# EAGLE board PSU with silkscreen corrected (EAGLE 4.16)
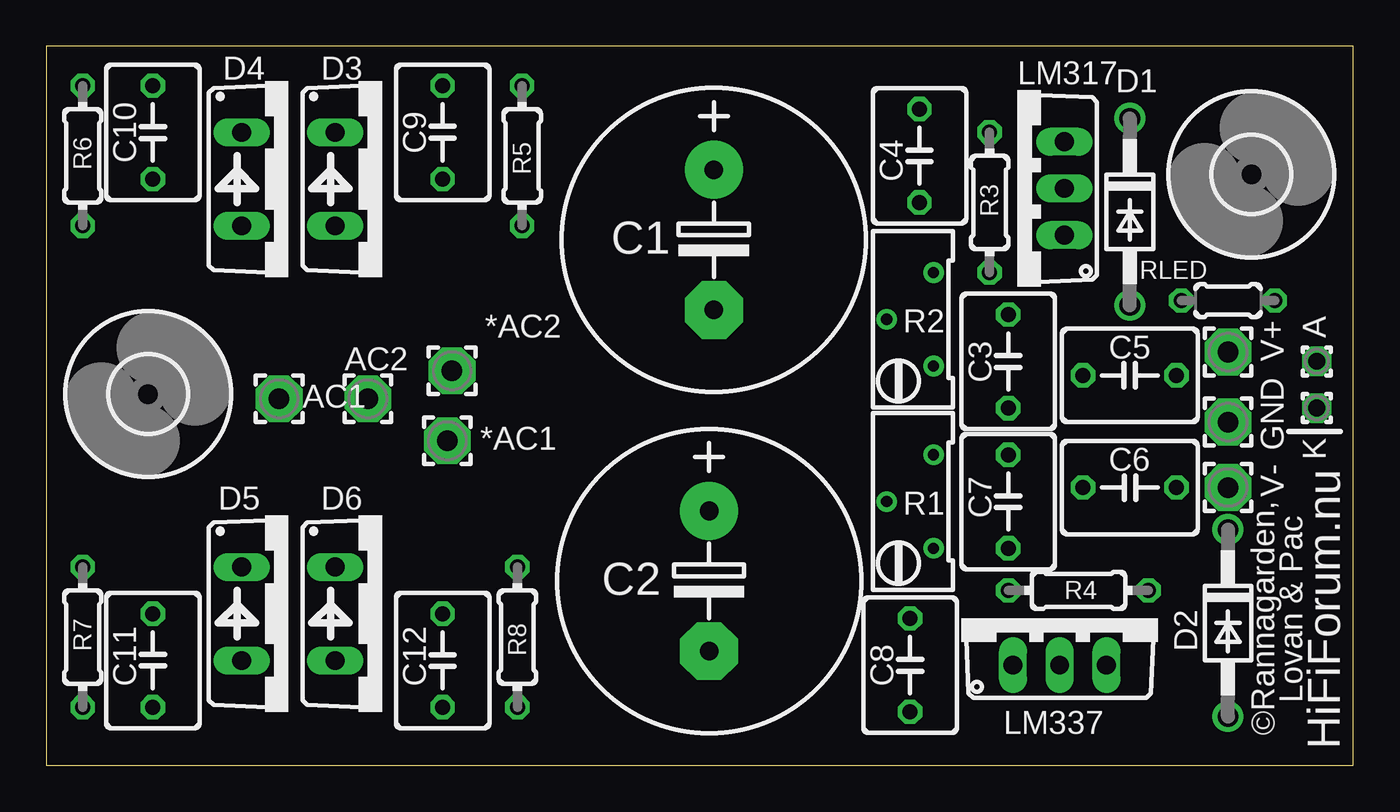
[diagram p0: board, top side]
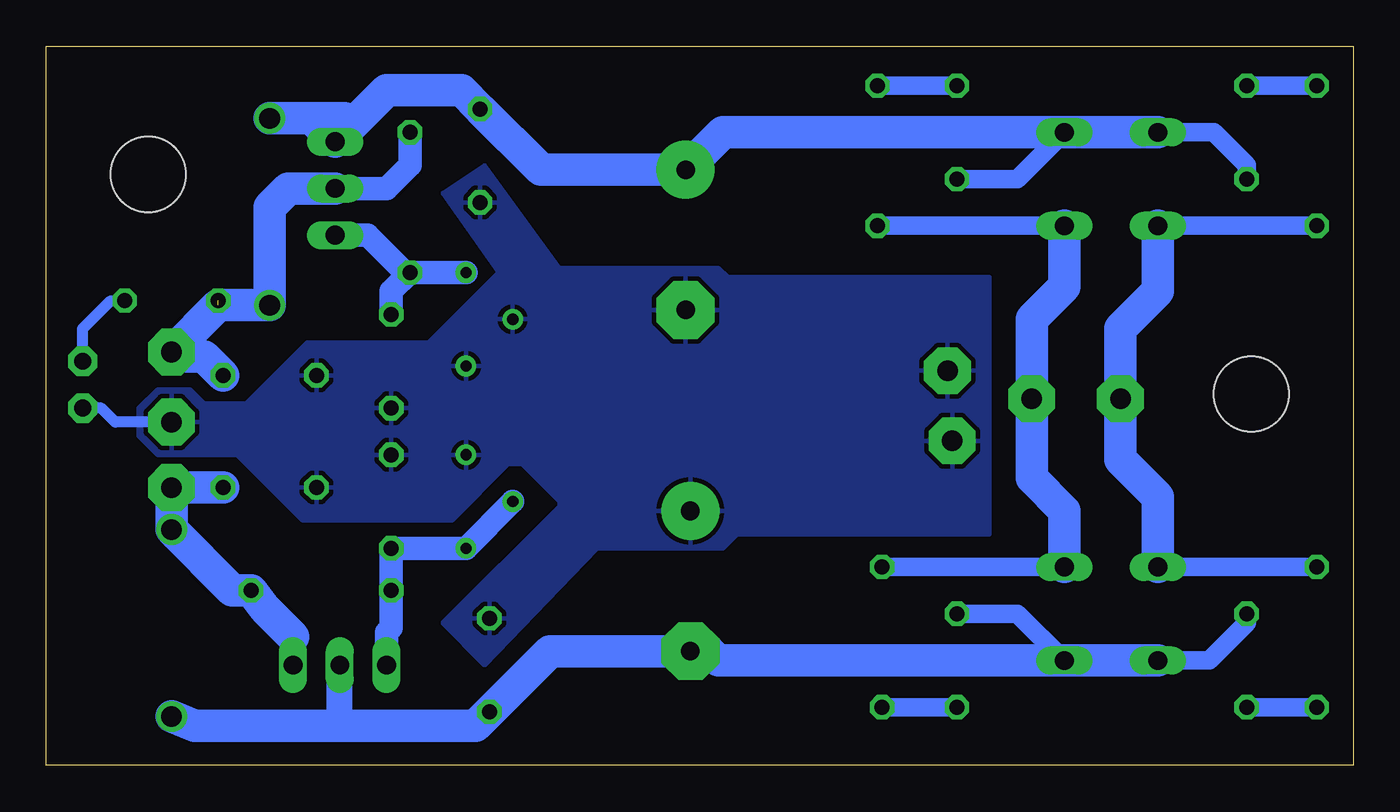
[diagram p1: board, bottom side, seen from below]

Size 71.04 x 39.11 mm. Coordinates in mm from the lower left corner, seen from the top.
Outline: 0,0 71.04,0 71.04,39.11 0,39.11 0,0
Copper layers (1*16): Top 0.035mm / dielectric 1.5mm / Bottom 0.035mm
Design rules "10mils": minimum track width 10mil, minimum drill 24mil, track to track 10mil, track to pad 10mil, pad to pad 10mil, via to via 10mil, smd to smd 10mil, copper to edge 40mil, drill to drill 10mil, minimum pad ring 10mil, minimum via ring 8mil, stop-mask expansion 0mil, vias tented up to drill 0mil, thermal gap 10mil

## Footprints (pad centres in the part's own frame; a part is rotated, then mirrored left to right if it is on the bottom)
2,54/1,1 = drill 1.118 pad 2.54 octagon: 1 0,0
1,6/0,9 = drill 0.914 pad 1.6 octagon: 1 0,0
E7,5-16 = drill 1.016 pad 3.15 round: + -3.81,0 | drill 1.016 pad 3.15 octagon: - 3.81,0
C050-050X075 = drill 0.813 octagon: 1 -2.54,0; 2 2.54,0
DO41-10 = drill 1.118 round: A 5.08,0; C -5.08,0
DO220S = drill 1.016 long: A 2.54,-2.54; C -2.54,-2.54
TO220V = drill 1.016 long: 1 -2.54,-2.54; 2 0,-2.54; 3 2.54,-2.54
RTRIM64Y = drill 0.61 round: 1 0,-2.54; 2 -2.54,0; 3 0,2.54
0204/7 = drill 0.813 octagon: 1 -3.81,0; 2 3.81,0
0204/5 = drill 0.813 octagon: 1 -2.54,0; 2 2.54,0
4,1 = hole 4.1: 0,0

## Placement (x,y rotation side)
*AC1  [2,54/1,1]  21.81,17.65 0 top
*AC2  [2,54/1,1]  22.06,21.46 0 top
A  [1,6/0,9]  69.05,21.97 90 top
AC1  [2,54/1,1]  12.66,19.93 0 top
AC2  [2,54/1,1]  17.49,19.93 0 top
C1  [E7,5-16]  36.28,28.57 270 top
C2  [E7,5-16]  36.03,10.03 270 top
C3  [C050-050X075]  52.29,21.97 270 top
C4  [C050-050X075]  47.46,33.14 270 top
C5  [C050-050X075]  58.89,21.2 180 top
C6  [C050-050X075]  58.89,15.11 0 top
C7  [C050-050X075]  52.29,14.35 270 top
C8  [C050-050X075]  46.95,5.46 270 top
C9  [C050-050X075]  21.55,34.41 90 top
C10  [C050-050X075]  5.8,34.41 270 top
C11  [C050-050X075]  5.8,5.71 90 top
C12  [C050-050X075]  21.55,5.71 270 top
D1  [DO41-10]  58.89,30.09 270 top
D2  [DO41-10]  64.22,7.74 270 top
D3  [DO220S]  18.25,31.87 270 top
D4  [DO220S]  13.17,31.87 270 top
D5  [DO220S]  13.17,8.25 270 top
D6  [DO220S]  18.25,8.25 270 top
GND  [2,54/1,1]  64.22,18.66 0 top
K  [1,6/0,9]  69.05,19.43 0 top
LM317  [TO220V]  52.79,31.36 90 top
LM337  [TO220V]  55.08,8 0 top
R1  [RTRIM64Y]  48.22,14.35 0 top
R2  [RTRIM64Y]  48.22,24.25 0 top
R3  [0204/7]  51.27,30.6 90 top
R4  [0204/7]  56.1,9.52 180 top
R5  [0204/7]  25.87,33.14 90 top
R6  [0204/7]  1.99,33.14 90 top
R7  [0204/7]  1.99,6.98 90 top
R8  [0204/7]  25.62,6.98 90 top
RLED  [0204/5]  64.22,25.27 180 top
U$1  [4,1]  65.49,32.13 0 top
U$2  [4,1]  5.55,20.19 0 top
V+  [2,54/1,1]  64.22,22.47 0 top
V-  [2,54/1,1]  64.22,15.11 0 top

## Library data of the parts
*AC1 *AC2 A AC1 AC2 GND K V+ V- = wirepad
C1-C12 R1-R8 RLED = rcl
D1-D6 = diode
LM317 LM337 = Rannagarden
U$1 U$2 = holes

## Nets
GND: *AC1.1 *AC2.1 C1.- C2.+ C3.2 C4.2 C5.2 C6.1 C7.1 C8.1 GND.1 K.1 R1.3 R2.1 R2.2
N$1: AC2.1 D3.A D6.C R5.1 R8.2
N$2: C7.2 LM337.1 R1.1 R1.2 R4.2
N$3: C3.1 LM317.1 R2.3 R3.1
N$4: A.1 RLED.1
N$5: AC1.1 D4.A D5.C R6.1 R7.2
N$6: C2.- C8.2 C11.2 C12.1 D2.A D5.A D6.A LM337.2
N$7: C6.2 D2.C LM337.3 R4.1 V-.1
N$8: C5.1 D1.A LM317.2 R3.2 RLED.2 V+.1
N$9: C9.2 R5.2
N$10: C1.+ C4.1 C9.1 C10.2 D1.C D3.C D4.C LM317.3
N$11: C10.1 R6.2
N$12: C11.1 R7.1
N$13: C12.2 R8.1

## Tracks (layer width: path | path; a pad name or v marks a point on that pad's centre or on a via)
GND
  Bottom 0.61: K.1 68.03,19.43 67.27,18.66 GND.1
  pour Bottom: 19.77,26.54 34,26.54 34.51,27.05 43.14,27.05 47.21,32.63 49.49,31.11 46.44,26.79 50.25,22.98 56.86,22.98 60.16,19.68 62.45,19.68 63.21,20.44 64.99,20.44 66,19.43 66,17.9 64.99,16.89 60.67,16.89 57.11,13.33 48.98,13.33 45.94,16.38 45.17,16.38 43.14,14.35 43.14,14.09 49.49,7.74 47.21,5.46 41.11,11.81 34.25,11.81 33.49,12.57 19.77,12.57
N$1
  Bottom 1.016: D3.A R5.1 | D6.C R8.2
  Bottom 1.778: D3.A 15.71,26.03 17.49,24.25 AC2.1 17.49,15.62 15.71,13.84 D6.C
N$2
  Bottom 1.27: R1.2 R1.1 C7.2 R4.2 52.29,7.49 52.54,7.23 LM337.1
N$3
  Bottom 1.27: R2.3 R3.1 | C3.1 52.29,25.78 R3.1 | R3.1 51.52,26.79 53.56,28.82 LM317.1
N$4
  Bottom 0.61: RLED.1 67.53,25.27 69.05,23.74 A.1
N$5
  Bottom 1.016: D4.A R6.1 | R7.2 D5.C
  Bottom 1.778: D4.A 10.63,25.78 12.66,23.74 AC1.1 12.66,16.63 10.63,14.6 D5.C
N$6
  Bottom 1.016: C11.2 5.8,7.74 7.84,5.71 D5.A | C12.1 18.25,8.25 D6.A
  Bottom 1.422: 55.08,2.15 LM337.2
  Bottom 1.778: D2.A 62.95,2.15 55.08,2.15 47.71,2.15 C8.2 43.65,6.22 C2.- 35.01,6.22 34.51,5.71 D6.A D5.A
N$7
  Bottom 1.422: LM337.3 57.62,6.98
  Bottom 1.778: C6.2 V-.1 D2.C 60.92,9.52 R4.1 59.14,8.5 57.62,6.98
N$8  (1 unrouted)
  Bottom 1.27: LM317.2 52.54,31.36 51.27,32.63 R3.2
  Bottom 1.778: LM317.2 57.87,31.36 58.89,30.35 D1.A 61.68,25.01 V+.1 63.97,22.22 62.45,22.22 C5.1
N$9
  Bottom 1.016: C9.2 R5.2
N$10
  Bottom 1.016: C10.2 5.8,32.63 7.58,34.41 D4.C | C9.1 18.25,31.87 D3.C
  Bottom 1.778: 56.86,35.17 56.6,35.17 LM317.3 52.54,36.7 48.48,36.7 C4.1 44.16,32.38 C1.+ 34.25,34.41 D3.C D4.C | 56.86,35.17 D1.C | 56.86,35.17 54.83,35.17
N$11
  Bottom 1.016: R6.2 C10.1
N$12
  Bottom 1.016: R7.1 C11.1
N$13
  Bottom 1.016: C12.2 R8.1

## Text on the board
tPlace: Lovan & Pac | ©Rannagarden, | HiFiForum.nu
